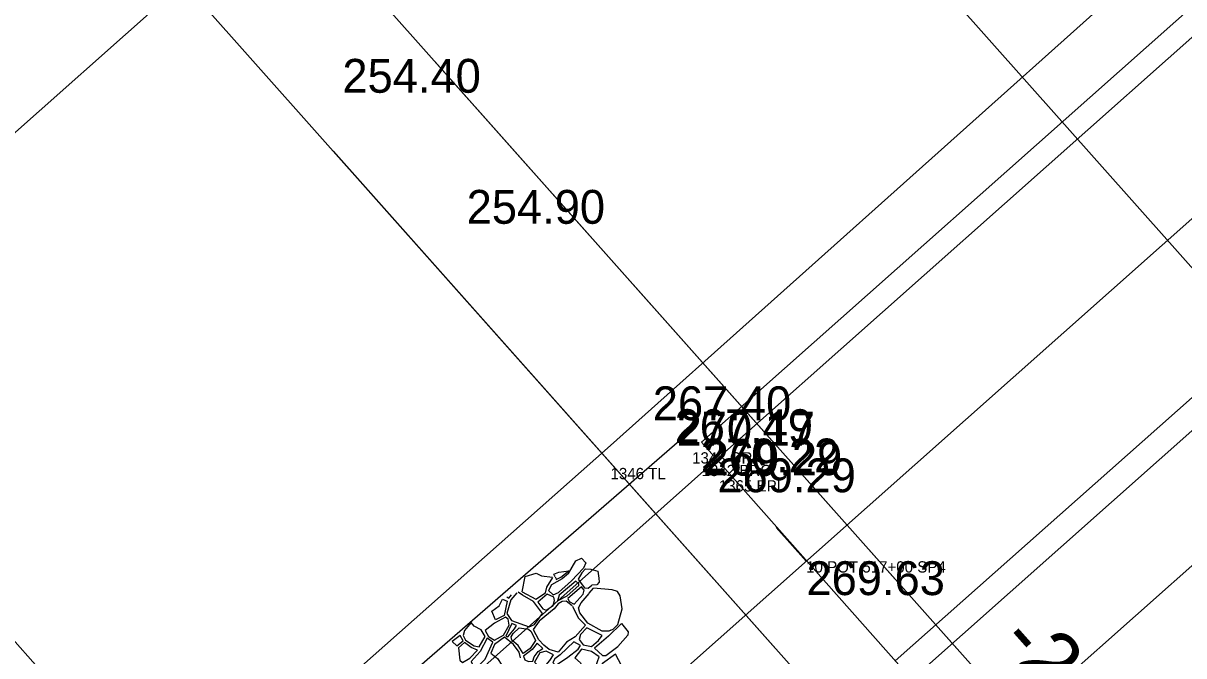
# Model space of a CAD drawing. Extents: x 49683 to 58852, y 49525 to 54803.
# Drawn here: x 53372.4 to 53475.3, y 51472.3 to 51528.4 of the extents above; entities that cross this region are included whole.
import ezdxf

# ---------------------------------------------------------------- set-up
doc = ezdxf.new("R2010")
doc.units = 0
for name, color, linetype in [('Level 1', 7, 'Continuous'), ('Level 11', 7, 'Continuous'), ('Level 13', 7, 'Continuous'), ('Level 15', 7, 'Continuous'), ('Level 16', 7, 'Continuous'), ('Level 3', 7, 'Continuous'), ('Level 32', 7, 'Continuous'), ('Level 5', 7, 'Continuous'), ('Level 50', 7, 'Continuous'), ('Level 51', 7, 'Continuous'), ('Level 53', 7, 'Continuous'), ('Level 55', 7, 'Continuous'), ('Level 57', 7, 'Continuous'), ('Level 61', 7, 'Continuous'), ('Level 63', 7, 'Continuous'), ('Level 7', 7, 'Continuous')]:
    doc.layers.add(name, color=color, linetype=linetype)

msp = doc.modelspace()

# ---------------------------------------------------------------- linework, layer by layer
at = {"layer": 'Level 1'}
for p, q in [((52544.81, 50683.3), (55534.58, 53340.86)), ((53441.83, 51480.65), (53439.17, 51483.64))]:
    msp.add_line(p, q, dxfattribs=at)
at = {"layer": 'Level 11'}
for p, q in [((53424.49, 51490.93), (53894.91, 51911.93)), ((53157.7, 51254.45), (53424.49, 51490.93))]:
    msp.add_line(p, q, dxfattribs=at)
at = {"layer": 'Level 13'}
msp.add_line((53573.51, 51698.05), (53335.95, 51486.88), dxfattribs=at)
at = {"layer": 'Level 15'}
msp.add_line((53460.73, 51466.68), (53909.18, 51865.3), dxfattribs=at)
at = {"layer": 'Level 16'}
for points in [[(53420.78, 51479.56), (53421.42, 51480.68), (53421.93, 51480.93), (53422.31, 51480.5), (53422.09, 51480.03), (53421.03, 51478.91)], [(53416.65, 51477.93), (53416.93, 51479.29), (53417.89, 51479.59), (53418.38, 51479.37), (53419.36, 51479.24)], [(53420.78, 51479.56), (53420.21, 51479.08), (53419.25, 51478.56), (53419, 51478.06), (53419.41, 51477.67), (53419.89, 51477.88), (53421.03, 51478.91)], [(53419.58, 51479.31), (53419.53, 51479.4), (53419.48, 51479.52), (53419.9, 51479.68), (53420.81, 51479.81)], [(53419.58, 51479.28), (53419.65, 51479.15), (53419.69, 51479.03), (53420.1, 51479.24), (53420.81, 51479.81)], [(53420.77, 51479.79), (53420.7, 51479.73)], [(53422.27, 51479.97), (53421.94, 51479.62), (53421.64, 51479.07), (53421.99, 51478.55), (53422.2, 51478.28), (53422.52, 51478.25), (53422.85, 51478.53)], [(53422.27, 51479.97), (53422.76, 51479.95), (53423.36, 51479.76), (53423.46, 51479.14), (53423.5, 51478.8), (53423.29, 51478.56), (53422.85, 51478.53)], [(53416.65, 51477.93), (53417.88, 51477.29), (53418.73, 51477.84), (53418.86, 51478.36), (53419.38, 51479.2)], [(53416.19, 51477.86), (53415.66, 51477.22), (53415.3, 51476.03), (53415.73, 51475.41), (53417.28, 51474.85), (53417.75, 51475.03), (53418.45, 51476.02), (53417.68, 51477.09), (53416.68, 51477.63), (53416.31, 51477.91)], [(53415.3, 51477.49), (53415.48, 51477.38), (53415.72, 51477.66)], [(53424.51, 51474.55), (53424.33, 51474.46), (53423.75, 51474.46), (53422.49, 51475.15), (53421.77, 51476.08), (53421.66, 51476.53), (53421.89, 51476.97), (53422.59, 51477.8)], [(53422.61, 51477.82), (53422.97, 51478.26)], [(53424.51, 51474.55), (53424.72, 51474.62), (53425.13, 51475.04), (53425.52, 51476.42), (53425.36, 51477.58), (53425.12, 51477.98), (53424.64, 51478.12), (53422.97, 51478.26)], [(53421.1, 51476.69), (53420.56, 51477.1), (53420.21, 51477.09), (53419.85, 51476.88), (53419.51, 51476.44), (53418.16, 51475.34), (53417.64, 51474.6), (53418.12, 51473.71)], [(53421.13, 51476.67), (53421.62, 51475.64), (53422.27, 51474.97), (53421.36, 51473.94), (53420.58, 51473.49), (53419.85, 51472.58), (53419.05, 51472.83), (53418.57, 51473.21), (53418.15, 51473.68)], [(53424.31, 51474.01), (53425.48, 51475.14), (53426.07, 51474.4), (53426.04, 51474.1), (53425.15, 51473.09)], [(53416.5, 51472.08), (53416.4, 51472.58), (53415.9, 51473.28), (53415.09, 51473.91), (53414.22, 51473.26), (53413.87, 51472.49), (53414.49, 51472.04), (53415.25, 51470.85)], [(53424.31, 51474.01), (53423.08, 51472.94), (53423.78, 51472.29), (53424.07, 51472.29), (53425.15, 51473.09)]]:
    msp.add_lwpolyline(points, dxfattribs=at)
for points in [[(53421.42, 51478.89), (53419.93, 51477.64), (53419.79, 51477.14), (53420.66, 51477.57), (53421.68, 51478.49), (53421.67, 51478.65)], [(53421.92, 51478.39), (53420.72, 51477.36), (53420.84, 51477.09), (53421.27, 51476.86), (53422.06, 51477.72), (53422.17, 51478.1)], [(53414.91, 51477.28), (53415.34, 51477.12), (53415.06, 51475.84), (53414.31, 51475.46), (53413.98, 51476.23), (53414.63, 51476.71)], [(53418.04, 51477.03), (53418.48, 51476.42), (53418.8, 51476.32), (53419.41, 51476.74), (53419.53, 51477.18), (53419.47, 51477.48), (53418.88, 51477.73)], [(53413.38, 51473.98), (53413.02, 51474.58), (53412.41, 51474.88), (53412.14, 51475.22), (53411.55, 51474.51), (53411.42, 51474.08), (53411.64, 51473.66), (53412.41, 51473.14), (53412.85, 51473.06)], [(53415.17, 51475.68), (53414.2, 51475.15), (53413.38, 51474.52), (53413.69, 51473.97), (53414.21, 51473.64), (53415, 51474.11), (53415.5, 51474.98), (53415.43, 51475.52)], [(53415.75, 51475.13), (53415.2, 51474.02), (53415.39, 51473.96), (53415.99, 51474.66), (53416.16, 51474.96)], [(53417.85, 51473.63), (53417.36, 51472.9), (53416.76, 51472.47), (53416.32, 51473.18), (53415.74, 51473.66), (53415.68, 51473.94), (53415.87, 51474.24), (53416.39, 51474.75), (53417.21, 51474.64), (53417.47, 51474.43)], [(53423.75, 51474.08), (53422.4, 51474.75), (53421.84, 51474.16), (53421.71, 51473.7), (53422.08, 51473.25), (53422.81, 51473.08), (53423.42, 51473.61)], [(53411.16, 51474.06), (53410.47, 51473.53), (53410.88, 51473.14), (53411.43, 51473.59)], [(53411.56, 51473.46), (53411.02, 51472.98), (53411.15, 51471.88), (53411.38, 51471.67), (53412.02, 51472.06), (53412.69, 51472.78), (53412.15, 51473.01)], [(53413.55, 51473.82), (53412.93, 51472.66), (53412.13, 51471.75), (53412.32, 51471.38), (53412.68, 51471.27), (53413.37, 51471.97), (53414.07, 51473.49)], [(53417.99, 51473.38), (53417.56, 51472.83), (53416.78, 51472.24), (53416.9, 51471.91), (53417.21, 51471.77), (53417.6, 51471.78), (53417.74, 51472.17), (53418.08, 51472.65), (53418.5, 51472.92)], [(53421.82, 51473.19), (53421.25, 51473.51), (53420.03, 51472.36), (53419.56, 51471.99), (53419.37, 51471.67), (53419.62, 51471.42), (53420.71, 51472.16), (53421.63, 51472.85)], [(53419.44, 51472.36), (53418.78, 51472.68), (53418.24, 51472.54), (53417.76, 51471.7), (53418.24, 51471.2), (53418.78, 51471.46), (53419.12, 51471.85)], [(53423.49, 51472.17), (53422.81, 51472.66), (53421.92, 51472.86), (53421.32, 51472.1), (53421.82, 51471.63), (53422.27, 51470.68), (53422.5, 51470.68), (53423.19, 51471.36)], [(53424.92, 51472.4), (53423.78, 51471.58), (53422.5, 51469.97), (53423.17, 51469.37), (53423.99, 51468.87), (53425.73, 51470.9)]]:
    msp.add_lwpolyline(points, close=True, dxfattribs=at)
at = {"layer": 'Level 3'}
for p, q in [((53434.09, 51489.84), (53883.27, 51889.18)), ((53449.72, 51471.81), (53898.74, 51870.57)), ((53162.5, 51248.32), (53434.09, 51489.84))]:
    msp.add_line(p, q, dxfattribs=at)
at = {"layer": 'Level 5'}
for p, q in [((53432.56, 51491.2), (53881.99, 51890.68)), ((53900.07, 51869.4), (53451.19, 51470.16)), ((53451.19, 51470.16), (53432.56, 51491.2))]:
    msp.add_line(p, q, dxfattribs=at)
at = {"layer": 'Level 50'}
for p, q in [((53424.03, 51565.17), (53583.47, 51385.79)), ((53375.7, 51562.35), (53575, 51338.12)), ((53386.66, 51531.95), (53546.1, 51352.57)), ((53349.29, 51498.74), (53508.73, 51319.36))]:
    msp.add_line(p, q, dxfattribs=at)
at = {"layer": 'Level 53'}
for p, q in [((53408.91, 51524.98), (53541.79, 51375.5)), ((53399.94, 51517.01), (53532.82, 51367.52))]:
    msp.add_line(p, q, dxfattribs=at)
at = {"layer": 'Level 7'}
msp.add_line((53431.72, 51492.32), (53399.95, 51464.72), dxfattribs=at)

# ---------------------------------------------------------------- texts
at = {"layer": 'Level 32'}
for s, p in [('254.40', (53400.73, 51522.2)), ('254.90', (53411.74, 51510.58)), ('267.40', (53428.24, 51493.16)), ('267.49', (53430.17, 51491.13)), ('270.17', (53430.35, 51490.91)), ('270.22', (53432.49, 51488.53)), ('269.29', (53432.76, 51488.28)), ('269.29', (53433.97, 51486.77)), ('269.63', (53441.86, 51477.65))]:
    msp.add_text(s, height=3, dxfattribs=at).set_placement(p)
at = {"layer": 'Level 51'}
msp.add_text('10 POT 517+00 SP4', height=1, dxfattribs=at).set_placement((53441.83, 51479.65))
at = {"layer": 'Level 53'}
msp.add_text('1365 EPL', height=1, dxfattribs=at).set_placement((53434.09, 51486.84))
at = {"layer": 'Level 55'}
msp.add_text('1342 BRC', height=1, dxfattribs=at).set_placement((53432.56, 51488.2))
at = {"layer": 'Level 57'}
msp.add_text('1343 GRA', height=1, dxfattribs=at).set_placement((53431.72, 51489.32))
at = {"layer": 'Level 61'}
msp.add_text('1346 TL', height=1, dxfattribs=at).set_placement((53424.49, 51487.93))
at = {"layer": 'Level 63'}
msp.add_text('-2.08', height=5.25, rotation=311.6335, dxfattribs=at).set_placement((53458.71, 51473.38))

doc.saveas('drawing.dxf')
